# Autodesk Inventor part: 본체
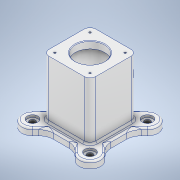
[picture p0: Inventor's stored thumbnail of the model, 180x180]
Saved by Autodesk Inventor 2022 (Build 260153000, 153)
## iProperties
Created: 2022-05
Part Number: 본체
Material: 알루미늄 6061
Document SubType Name: Modeling
Designer: Admin
Mass: 1072.62 g
Surface Area: 876.974 cm^2
Volume: 397.266 cm^3
Density: 2.7 g/cm^3
Appearance: 알루미늄 - 평지
Author: Admin
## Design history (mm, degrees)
sketch "스케치1"
  geometry: L1 (40, 40)-(-40, 40); L2 (-40, 40)-(-40, -40); L3 (-40, -40)-(40, -40); L4 (40, -40)-(40, 40); L5 (40, 40)-(-40, -40); L6 (-40, 40)-(40, -40); 1 further point
  constraints: 12 end point, 2 midpoint, 2 parallel, 1 horizontal, 1 perpendicular
  dimensions: "d0" = 80 distance of L3.end L2.end; "d1" = 80 distance of L2.end L1.end
extrude "돌출1" new body sketch "스케치1" distance "d2" = 110; taper "d3" = 0 deg
sketch "스케치2"
  geometry: L1 (40, 40)-(40, -40) reference; L2 (-40, 40)-(40, 40) reference; L3 (-40, -40)-(-40, 40) reference; L4 (40, -40)-(-40, -40) reference; L5 (-104.238, 0)-(104.238, 0) reference; L6 (0, -104.238)-(0, 104.238) reference; L7 (-23.544, 49)-(23.544, 49); L8 (49, 23.544)-(49, -23.544); L9 (23.544, -49)-(-23.544, -49); L10 (-49, -23.544)-(-49, 23.544); L11 (-49, 49)-(49, -49); L12 (49, 49)-(-49, -49); L13 (-49, 49)-(49, -49); L14 (-49, -49)-(49, 49); L15 (49, 23.544)-(61.728, 36.272); L16 (61.728, -36.272)-(49, -23.544); L17 (36.272, 61.728)-(23.544, 49); L18 (-23.544, 49)-(-36.272, 61.728); L19 (-61.728, 36.272)-(-49, 23.544); L20 (-49, -23.544)-(-61.728, -36.272); L21 (-36.272, -61.728)-(-23.544, -49); L22 (23.544, -49)-(36.272, -61.728); A1 r 18 centre (-49, 49) between (-36.272, 61.728) and (-61.728, 36.272); A2 r 18 centre (49, -49) between (36.272, -61.728) and (61.728, -36.272); A3 r 18 centre (-49, -49) between (-61.728, -36.272) and (-36.272, -61.728); A4 r 18 centre (49, 49) between (61.728, 36.272) and (36.272, 61.728); 1 further point
  constraints: 36 end point, 16 tangent, 12 equal length, 8 point on circle, 4 centre point, 4 midpoint, 1 horizontal, 1 perpendicular, 1 point on line
  dimensions: "d7" = 98 distance of L11.end L12.end; "d8" = 98 distance of L12.start L11.end; "d9" = 36 diameter of A2; "d10" = 36 diameter of A4; "d11" = 49 distance between parallel lines of L6 L8; "d12" = 49 distance between parallel lines of L6 L10; "d13" = 98 distance between parallel lines of L7 L9; "d14" = 49 distance between parallel lines of L7 L5; "d15" = 45 deg angle of L5 L14; "d16" = 45 deg angle of L5 L11
extrude "돌출2" join sketch "스케치2" distance "d17" = 12; taper "d18" = 0 deg
sketch "스케치3"
  geometry: L1 (-61.728, -36.272)-(-49, -23.544) reference; L2 (-49, -23.544)-(-49, 23.544) reference; L3 (-49, 23.544)-(-61.728, 36.272) reference; L4 (-36.272, 61.728)-(-23.544, 49) reference; L5 (-23.544, 49)-(23.544, 49) reference; L6 (23.544, 49)-(36.272, 61.728) reference; L7 (61.728, 36.272)-(49, 23.544) reference; L8 (49, 23.544)-(49, -23.544) reference; L9 (49, -23.544)-(61.728, -36.272) reference; L10 (36.272, -61.728)-(23.544, -49) reference; L11 (23.544, -49)-(-23.544, -49) reference; L12 (-23.544, -49)-(-36.272, -61.728) reference; A1 r 18 centre (-49, 49) between (-36.272, 61.728) and (-61.728, 36.272) reference; A2 r 18 centre (49, 49) between (61.728, 36.272) and (36.272, 61.728) reference; A3 r 18 centre (49, -49) between (36.272, -61.728) and (61.728, -36.272) reference; A4 r 18 centre (-49, -49) between (-61.728, -36.272) and (-36.272, -61.728) reference; 5 further points
  constraints: 4 coincident
hole "구멍1" sketch "스케치3" at (49, 49), (49, -49), (-49, 49), (-49, -49) diameter "d19" = 10; stored, may be unused: countersink angle "d23" = 90 deg, drill point angle "d25" = 118 deg; dims "d20" = 11, "d21" = 18, "d22" = 4, "d24" = 13
sketch "스케치4"
  geometry: L1 (40, -132)-(40, 22) reference; L2 (16.456, -98)-(63.544, -98) reference; C1 r 20 at (40, -49); 1 further point
  constraints: 1 centre point, 1 point on line
  dimensions: "d26" = 40 diameter of C1; "d27" = 49 distance from line of L2 C1.centre
extrude "돌출3" join sketch "스케치4" distance "d28" = 15; taper "d29" = 0 deg
sketch "스케치5"
  geometry: C1 r 20 at (0, 0) reference; C2 r 15 at (0, 0); 1 further point
  constraints: 1 centre point, 1 coincident
  dimensions: "d30" = 30 diameter of C2
extrude "돌출4" cut sketch "스케치5" distance "d31" = 8; taper "d32" = 0 deg
sketch "스케치6"
  geometry: L1 (-22, 0)-(132, 0) reference; L2 (0, -93.8)-(0, 93.8) reference; L3 (110, -40)-(110, 40) reference; L4 (110, -25)-(98, -25); L5 (98, -25)-(98, -35); L6 (98, -35)-(12, -35); L7 (12, -35)-(12, -25); L8 (12, -25)-(0, -25); L9 (0, 23.544)-(0, -23.544) reference; L10 (110, -25)-(110, 0); L11 (110, 0)-(0, 0); L12 (0, 0)-(0, -25); 1 further point
  constraints: 16 end point, 4 point on line, 3 perpendicular, 2 collinear, 1 horizontal, 1 midpoint
  dimensions: "d33" = 70 diameter of L6 L1; "d34" = 50 diameter of L8 L1; "d35" = 86 distance of L5.end L6.end; "d36" = 12 distance of L4.start L4.end
revolve "회전1" sketch "스케치6" stored, may be unused: angle "d37" = 90 deg
sketch "스케치7"
  geometry: C1 r 15 at (0, 0) reference; C2 r 15 at (0, 0) reference; C3 r 12.5 at (0, 0); 1 further point
  constraints: 1 centre point, 1 coincident
  dimensions: "d38" = 25 diameter of C3
extrude "돌출5" cut sketch "스케치7" stored distance "d39" = 8; taper "d40" = 0 deg
fillet "모깎기1" dims "d41" = 3
sketch "스케치8"
  geometry: L1 (0, -98)-(80, -98) reference; L2 (80, -98)-(80, 0) reference; L3 (0, 0)-(80, 0) reference; L4 (0, -98)-(0, 0) reference; L5 (40, -132)-(40, 22) reference; C1 r 20 at (40, -49) reference; 2 further points
  constraints: 1 point on line, 1 other
  dimensions: "d42" = 10 distance from line of L3 point (40, -10)
feature "엠보싱1" sketch "스케치8" dims "d0" = 80, "d1" = 80, "d7" = 98, "d8" = 98, "d9" = 36, "d10" = 36, "d11" = 49, "d12" = 49, "d13" = 98, "d14" = 49, "d15" = 45 deg, "d16" = 45 deg, "d43" = 0.5, "d44" = 0
chamfer "모따기1" distance "d45" = 1; stored, may be unused: second distance "d46" = 2, angle "d47" = 45 deg
chamfer "모따기2" distance "d48" = 1; stored, may be unused: second distance "d49" = 2, angle "d50" = 45 deg
chamfer "모따기3" distance "d51" = 1; stored, may be unused: second distance "d52" = 2, angle "d53" = 45 deg
fillet "모깎기2" dims "d54" = 10
fillet "모깎기3" dims "d55" = 3
fillet "모깎기4" dims "d56" = 3
sketch "스케치9"
  geometry: L1 (-30, -30)-(30, -30); L2 (30, -30)-(30, 30); L3 (30, 30)-(-30, 30); L4 (-30, 30)-(-30, -30); L5 (-30, -30)-(30, 30); L6 (30, -30)-(-30, 30); C1 r 35 at (0, 0) reference; A1 r 10 centre (30, -30) between (30, -40) and (40, -30) reference; 5 further points
  constraints: 12 end point, 4 coincident, 2 midpoint, 2 parallel, 1 horizontal, 1 perpendicular
  dimensions: "d57" = 60 distance of L3.end L2.end; "d58" = 60 distance of L2.end L1.end
hole "구멍2" sketch "스케치9" at (-30, 30), (30, 30), (-30, -30), (30, -30) diameter "d59" = 3.242; stored, may be unused: countersink angle "d63" = 90 deg, drill point angle "d65" = 118 deg; dims "d60" = 8, "d61" = 18, "d62" = 4, "d64" = 10
sketch "스케치10"
  geometry: L1 (30, 30)-(-30, 30); L2 (-30, 30)-(-30, -30); L3 (-30, -30)-(30, -30); L4 (30, -30)-(30, 30); L5 (30, 30)-(-30, -30); L6 (-30, 30)-(30, -30); C1 r 1.621 at (30, -30) reference; C2 r 1.621 at (-30, -30) reference; C3 r 1.621 at (-30, 30) reference; C4 r 1.621 at (30, 30) reference; A1 r 10 centre (-30, -30) between (-40, -30) and (-30, -40) reference; 5 further points
  constraints: 12 end point, 4 coincident, 2 midpoint, 2 parallel, 1 horizontal, 1 perpendicular
  dimensions: "d66" = 60 distance of L3.end L2.end (derived); "d67" = 60 distance of L2.end L1.end (derived)
hole "구멍3" sketch "스케치10" at (30, -30), (-30, -30), (-30, 30), (30, 30) diameter "d68" = 3.242; stored, may be unused: countersink angle "d72" = 90 deg, drill point angle "d74" = 118 deg; dims "d69" = 8, "d70" = 4, "d71" = 2, "d73" = 10
fillet "모깎기5" dims "d75" = 25
node "솔리드1"
node "투영된 루프1"
node "투영된 루프2"
node "투영된 루프3"
node "투영된 루프4"
node "투영된 루프5"
feature "A9D066F2-1C7D-4E18-AEED-F7BC21143FA4" dims "d19" = 10, "d20" = 11, "d21" = 18, "d22" = 4, "d23" = 90 deg, "d24" = 13, "d25" = 118 deg
